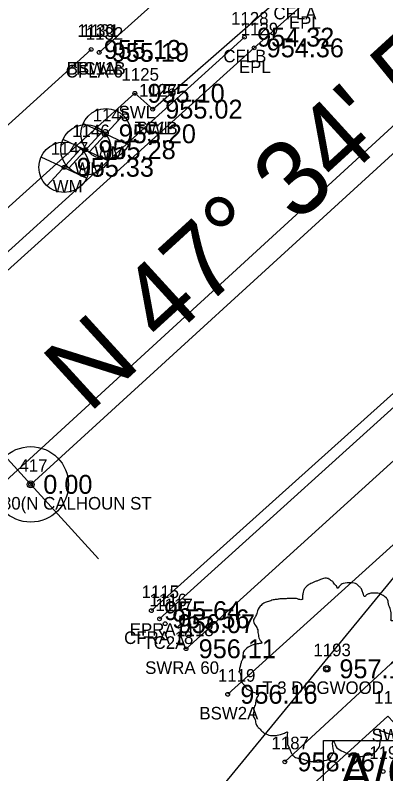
# Model space of a CAD drawing. Extents: x 1575382 to 1578175, y 1099175 to 1101955.
# Drawn here: x 1576354.3 to 1576383.7, y 1099534.1 to 1099594.4 of the extents above; entities that cross this region are included whole.
import ezdxf

# ---------------------------------------------------------------- set-up
doc = ezdxf.new("R2010")
doc.units = 0
for name, color, linetype in [('RD_EX_BldgApp', 7, 'Continuous'), ('RD_EX_BldgApp_txCode', 7, 'Continuous'), ('RD_EX_Conc', 7, 'Continuous'), ('RD_EX_Conc_txCode', 7, 'Continuous'), ('RD_EX_DR_Pipe', 7, 'Continuous'), ('RD_EX_Road', 7, 'Continuous'), ('RD_EX_Road_txCode', 7, 'Continuous'), ('RD_EX_TX_Conc_ELEV', 7, 'Continuous'), ('RD_EX_TX_Road_ELEV', 7, 'Continuous'), ('RD_EX_TX_UT_ELEV', 7, 'Continuous'), ('RD_EX_TX_VEG_ELEV', 7, 'Continuous'), ('RD_EX_UT', 7, 'Continuous'), ('RD_EX_UT_txCode', 7, 'Continuous'), ('RD_EX_VEG', 7, 'Continuous'), ('RD_EX_VEG_txCode', 7, 'Continuous'), ('RD_HC_Cl', 7, 'Continuous'), ('RD_HC_Data', 7, 'Continuous'), ('RD_HC_Data_Tic', 7, 'Continuous'), ('RD_HC_Survey_ELEV', 7, 'Continuous'), ('RD_HC_txCode', 7, 'Continuous'), ('RD_SMD_Locator', 7, 'Continuous')]:
    doc.layers.add(name, color=color, linetype=linetype)

msp = doc.modelspace()

# ---------------------------------------------------------------- linework, layer by layer
at = {"layer": 'RD_EX_BldgApp'}
msp.add_lwpolyline([(1576378.763, 1099531.771), (1576378.763, 1099536.771), (1576387.763, 1099536.771), (1576387.763, 1099531.771)], close=True, dxfattribs=at)
at = {"layer": 'RD_EX_Conc'}
for p, q in [((1576345.022, 1099567.755), (1576372.484, 1099592.673)), ((1576340.778, 1099574.008), (1576360.313, 1099591.697)), ((1576386.586, 1099545.179), (1576375.696, 1099535.084))]:
    msp.add_line(p, q, dxfattribs=at)
for points in [[(1576360.945, 1099591.467), (1576368.12, 1099597.926), (1576371.825, 1099601.361), (1576376.294, 1099605.493), (1576378.653, 1099607.482), (1576379.425, 1099608.864), (1576379.064, 1099610.368), (1576375.693, 1099614.257)], [(1576343.522, 1099569.964), (1576363.781, 1099588.213), (1576365.195, 1099586.953), (1576376.121, 1099596.515), (1576380.795, 1099600.714), (1576379.736, 1099601.846)], [(1576365.744, 1099546.452), (1576389.058, 1099567.543), (1576393.531, 1099571.514)], [(1576367.848, 1099544.074), (1576387.491, 1099561.904), (1576391.192, 1099565.202), (1576389.395, 1099567.132), (1576393.909, 1099571.093)], [(1576371.157, 1099540.455), (1576390.601, 1099558.016), (1576394.475, 1099561.498)], [(1576389.847, 1099541.582), (1576385.223, 1099537.281), (1576383.878, 1099538.711), (1576376.51, 1099532.017)]]:
    msp.add_lwpolyline(points, dxfattribs=at)
at = {"layer": 'RD_EX_DR_Pipe'}
msp.add_lwpolyline([(1576364.841, 1099525.95), (1576408.84, 1099579.579), (1576408.84, 1099579.579), (1576384.131, 1099602.876), (1576384.131, 1099602.876), (1576335.971, 1099659.822), (1576335.971, 1099659.822), (1576168.711, 1099756.104)], dxfattribs=at)
at = {"layer": 'RD_EX_Road'}
for points in [[(1576345.735, 1099566.974), (1576373.249, 1099591.824), (1576377.221, 1099595.34), (1576381.818, 1099599.483), (1576383.698, 1099601.102)], [(1576365.091, 1099547.103), (1576400.456, 1099578.873), (1576404.992, 1099582.283), (1576408.268, 1099583.268), (1576411.469, 1099582.29), (1576413.119, 1099580.849), (1576414.82, 1099582.112), (1576433.704, 1099559.004), (1576464.951, 1099521.111), (1576497.797, 1099481.911), (1576528.729, 1099444.459), (1576560.009, 1099406.61)]]:
    msp.add_lwpolyline(points, dxfattribs=at)
at = {"layer": 'RD_EX_UT'}
for p, q in [((1576173.795, 1099392.654), (1576417.784, 1099616.336)), ((1576360.14, 1099583.535), (1576362.807, 1099586.431)), ((1576359.658, 1099585.83), (1576363.289, 1099584.117)), ((1576358.539, 1099582.271), (1576361.207, 1099585.168)), ((1576358.058, 1099584.566), (1576361.689, 1099582.854)), ((1576356.806, 1099580.874), (1576359.474, 1099583.771)), ((1576356.325, 1099583.17), (1576359.956, 1099581.457))]:
    msp.add_line(p, q, dxfattribs=at)
for centre in [(1576361.492, 1099584.993), (1576359.891, 1099583.729), (1576358.158, 1099582.333)]:
    msp.add_circle(centre, 2, dxfattribs=at)
at = {"layer": 'RD_EX_VEG'}
for centre, radius in [((1576379.025, 1099542.481), 0.25), ((1576379.013, 1099542.462), 0.0001)]:
    msp.add_circle(centre, radius, dxfattribs=at)
for points in [[(1576379.157, 1099549.648), (1576378.857, 1099549.673), (1576378.533, 1099549.573), (1576378.283, 1099549.473), (1576378.058, 1099549.398), (1576377.833, 1099549.298), (1576377.533, 1099549.123), (1576377.308, 1099548.923), (1576377.183, 1099548.674), (1576377.133, 1099548.449), (1576377.083, 1099548.174), (1576377.083, 1099547.999), (1576376.958, 1099547.974), (1576376.808, 1099547.999), (1576376.558, 1099548.074), (1576376.308, 1099548.074), (1576376.059, 1099548.074), (1576375.709, 1099548.049), (1576375.359, 1099548.049), (1576375.084, 1099547.999), (1576374.759, 1099547.949), (1576374.384, 1099547.824), (1576374.034, 1099547.699), (1576373.735, 1099547.449), (1576373.485, 1099546.974), (1576373.36, 1099546.624), (1576373.21, 1099546.375), (1576373.36, 1099545.925), (1576373.535, 1099545.575), (1576373.56, 1099545.375), (1576373.635, 1099544.95), (1576373.735, 1099544.725), (1576373.86, 1099544.525), (1576373.785, 1099544.5), (1576373.41, 1099544.45), (1576373.11, 1099544.35), (1576372.685, 1099544.126), (1576372.46, 1099543.901), (1576372.36, 1099543.576), (1576372.335, 1099543.226), (1576372.235, 1099543.026), (1576372.16, 1099542.751), (1576372.135, 1099542.676), (1576372.085, 1099542.351), (1576372.185, 1099541.901), (1576372.21, 1099541.552), (1576372.335, 1099541.327), (1576372.485, 1099541.152), (1576372.66, 1099540.902), (1576373.06, 1099540.677), (1576373.385, 1099540.577), (1576373.585, 1099540.552), (1576373.41, 1099540.052), (1576373.36, 1099539.702), (1576373.235, 1099539.303), (1576373.235, 1099539.228), (1576373.185, 1099538.753), (1576373.335, 1099538.428), (1576373.41, 1099538.053), (1576373.585, 1099537.828), (1576373.86, 1099537.528), (1576374.184, 1099537.304), (1576374.684, 1099537.179), (1576375.084, 1099537.204), (1576375.659, 1099537.378), (1576375.909, 1099537.453), (1576375.884, 1099537.279), (1576375.909, 1099536.904), (1576375.909, 1099536.479), (1576376.059, 1099536.154), (1576376.159, 1099535.879), (1576376.308, 1099535.629), (1576376.633, 1099535.404), (1576377.033, 1099535.329), (1576377.458, 1099535.179), (1576377.908, 1099535.104), (1576378.408, 1099535.079), (1576379.007, 1099535.229), (1576379.282, 1099535.354), (1576379.382, 1099535.529), (1576379.582, 1099535.904), (1576379.532, 1099536.129), (1576379.557, 1099536.729), (1576379.657, 1099536.554), (1576379.832, 1099536.204), (1576380.332, 1099535.904), (1576380.732, 1099535.729), (1576381.206, 1099535.579), (1576381.506, 1099535.504), (1576381.981, 1099535.579), (1576382.356, 1099535.654), (1576382.731, 1099535.779), (1576383.031, 1099536.054), (1576383.205, 1099536.329), (1576383.255, 1099536.604), (1576383.33, 1099536.979), (1576383.38, 1099537.154)], [(1576383.38, 1099537.154), (1576383.305, 1099537.329), (1576383.255, 1099537.578), (1576383.33, 1099537.553), (1576383.505, 1099537.503), (1576383.78, 1099537.378), (1576384.005, 1099537.304), (1576384.33, 1099537.329), (1576384.605, 1099537.428), (1576385.055, 1099537.703), (1576385.33, 1099538.178), (1576385.604, 1099538.578), (1576385.679, 1099538.903), (1576385.629, 1099539.128), (1576385.604, 1099539.627), (1576385.404, 1099539.877), (1576385.354, 1099540.002), (1576385.255, 1099540.402), (1576385.33, 1099540.452), (1576385.604, 1099540.502), (1576385.979, 1099540.627), (1576386.254, 1099540.752), (1576386.479, 1099540.927), (1576386.554, 1099541.152), (1576386.529, 1099541.552), (1576386.579, 1099541.951), (1576386.504, 1099542.101), (1576386.404, 1099542.251), (1576386.329, 1099542.451), (1576386.179, 1099542.601), (1576386.079, 1099542.751), (1576385.979, 1099542.851), (1576385.854, 1099543.001), (1576385.679, 1099543.126), (1576385.529, 1099543.176), (1576385.479, 1099543.326), (1576385.629, 1099543.526), (1576385.679, 1099543.626), (1576385.704, 1099543.851), (1576385.929, 1099544.2), (1576385.979, 1099544.6), (1576385.929, 1099545.025), (1576385.879, 1099545.3), (1576385.729, 1099545.575), (1576385.529, 1099545.825), (1576385.404, 1099546), (1576385.23, 1099546.125), (1576384.905, 1099546.25), (1576384.655, 1099546.3), (1576384.305, 1099546.3), (1576384.105, 1099546.35), (1576384.13, 1099546.4), (1576384.13, 1099546.549), (1576384.13, 1099546.824), (1576384.055, 1099547.274), (1576383.905, 1099547.774), (1576383.905, 1099547.799), (1576383.805, 1099548.049), (1576383.58, 1099548.249), (1576383.405, 1099548.349), (1576383.205, 1099548.474), (1576382.956, 1099548.499), (1576382.656, 1099548.499), (1576382.381, 1099548.449), (1576382.181, 1099548.349), (1576382.006, 1099548.224), (1576381.931, 1099548.374), (1576381.831, 1099548.674), (1576381.781, 1099548.823), (1576381.631, 1099548.998), (1576381.406, 1099549.198), (1576380.956, 1099549.323), (1576380.332, 1099549.248), (1576380.032, 1099549.048), (1576379.882, 1099548.873), (1576379.832, 1099548.998), (1576379.632, 1099549.198), (1576379.532, 1099549.373), (1576379.357, 1099549.498), (1576379.207, 1099549.598), (1576379.107, 1099549.648)]]:
    msp.add_spline(points, degree=3, dxfattribs=at)
at = {"layer": 'RD_HC_Cl'}
msp.add_line((1576355.507, 1099557.135), (1576409.214, 1099606.208), dxfattribs=at)
at = {"layer": 'RD_HC_Data'}
for radius in [3, 0.282]:
    msp.add_circle((1576355.507, 1099557.135), radius, dxfattribs=at)
at = {"layer": 'RD_HC_Data_Tic'}
for q in [(1576350.111, 1099563.041), (1576360.904, 1099551.229)]:
    msp.add_line((1576355.507, 1099557.135), q, dxfattribs=at)
at = {"layer": 'RD_SMD_Locator'}
for centre in [(1576372.484, 1099592.673), (1576360.313, 1099591.697), (1576360.313, 1099591.697), (1576360.945, 1099591.467), (1576373.249, 1099591.824), (1576363.781, 1099588.213), (1576365.195, 1099586.953), (1576365.195, 1099586.953), (1576361.492, 1099584.993), (1576359.891, 1099583.729), (1576358.158, 1099582.333), (1576355.507, 1099557.135), (1576365.091, 1099547.103), (1576365.744, 1099546.452), (1576366.186, 1099546.067), (1576367.848, 1099544.074), (1576379.025, 1099542.481), (1576371.157, 1099540.455), (1576375.696, 1099535.084), (1576383.498, 1099534.323)]:
    msp.add_circle(centre, 0.15, dxfattribs=at)

# ---------------------------------------------------------------- texts
at = {"layer": 'RD_EX_BldgApp'}
msp.add_text('A/C', height=3, dxfattribs=at).set_placement((1576380.009, 1099532.775))
at = {"layer": 'RD_EX_BldgApp_txCode'}
msp.add_text('1190', height=1, dxfattribs=at).set_placement((1576382.395, 1099535.323))
at = {"layer": 'RD_EX_Conc_txCode'}
for s, p in [('CFLA', (1576374.789, 1099594.086)), ('1128', (1576371.421, 1099593.673)), ('1130', (1576359.211, 1099592.697)), ('1131', (1576359.534, 1099592.697)), ('1132', (1576359.882, 1099592.467)), ('CFLB', (1576370.807, 1099590.673)), ('CFLA 6', (1576358.291, 1099589.467)), ('BSW1B', (1576358.36, 1099589.697)), ('TC1A', (1576358.864, 1099589.697)), ('1125', (1576362.718, 1099589.213)), ('1126', (1576364.109, 1099587.953)), ('1127', (1576364.132, 1099587.953)), ('SWL', (1576362.489, 1099586.213)), ('TC1B', (1576363.762, 1099584.953)), ('SWL', (1576363.904, 1099584.953)), ('1116', (1576364.941, 1099547.452)), ('1117', (1576365.406, 1099547.067)), ('1118', (1576367.068, 1099545.074)), ('CFRA 18', (1576362.925, 1099544.452)), ('TC2A', (1576364.454, 1099544.067)), ('SWRA 60', (1576364.596, 1099542.074)), ('1119', (1576370.378, 1099541.455)), ('1186', (1576382.791, 1099539.711)), ('BSW2A', (1576368.905, 1099538.455)), ('SW2', (1576382.586, 1099536.711)), ('1187', (1576374.633, 1099536.084))]:
    msp.add_text(s, height=1, dxfattribs=at).set_placement(p)
at = {"layer": 'RD_EX_Road_txCode'}
for s, p in [('1129', (1576372.186, 1099592.824)), ('EPL', (1576376.017, 1099593.34)), ('EPL', (1576372.044, 1099589.824)), ('1115', (1576364.312, 1099548.103)), ('EPRA', (1576363.375, 1099545.103))]:
    msp.add_text(s, height=1, dxfattribs=at).set_placement(p)
at = {"layer": 'RD_EX_TX_Conc_ELEV'}
for s, p in [('954.32', (1576373.484, 1099591.923)), ('955.13', (1576361.313, 1099590.947)), ('955.13', (1576361.313, 1099590.947)), ('955.19', (1576361.945, 1099590.717)), ('955.10', (1576364.781, 1099587.463)), ('955.02', (1576366.195, 1099586.203)), ('955.02', (1576366.195, 1099586.203)), ('955.56', (1576366.744, 1099545.702)), ('956.07', (1576367.186, 1099545.317)), ('956.11', (1576368.848, 1099543.324)), ('956.16', (1576372.157, 1099539.705)), ('958.26', (1576376.696, 1099534.334))]:
    msp.add_text(s, height=1.5, dxfattribs=at).set_placement(p)
at = {"layer": 'RD_EX_TX_Road_ELEV'}
for s, p in [('954.36', (1576374.249, 1099591.074)), ('955.64', (1576366.091, 1099546.353))]:
    msp.add_text(s, height=1.5, dxfattribs=at).set_placement(p)
at = {"layer": 'RD_EX_TX_UT_ELEV'}
for s, p in [('955.20', (1576362.492, 1099584.243)), ('955.28', (1576360.891, 1099582.979)), ('955.33', (1576359.158, 1099581.583))]:
    msp.add_text(s, height=1.5, dxfattribs=at).set_placement(p)
at = {"layer": 'RD_EX_TX_VEG_ELEV'}
msp.add_text('957.19', height=1.5, dxfattribs=at).set_placement((1576380.025, 1099541.731))
at = {"layer": 'RD_EX_UT_txCode'}
for s, p in [('1145', (1576360.429, 1099585.993)), ('1146', (1576358.805, 1099584.729)), ('1147', (1576357.095, 1099583.333)), ('WM', (1576360.586, 1099582.993)), ('WM', (1576358.986, 1099581.729)), ('WM', (1576357.253, 1099580.333))]:
    msp.add_text(s, height=1, dxfattribs=at).set_placement(p)
at = {"layer": 'RD_EX_VEG_txCode'}
for s, p in [('1193', (1576377.962, 1099543.481)), ('T 3 DOGWOOD', (1576373.899, 1099540.481))]:
    msp.add_text(s, height=1, dxfattribs=at).set_placement(p)
at = {"layer": 'RD_HC_Data'}
msp.add_text('N 47%%d 34\' 54" E', height=6, rotation=42.41831, dxfattribs=at).set_placement((1576360.115, 1099562.699))
at = {"layer": 'RD_HC_Survey_ELEV'}
msp.add_text('0.00', height=1.5, dxfattribs=at).set_placement((1576356.507, 1099556.385))
at = {"layer": 'RD_HC_txCode'}
for s, p in [('417', (1576354.61, 1099558.135)), ('POT (10+00.00) S80(N CALHOUN ST', (1576342.334, 1099555.135))]:
    msp.add_text(s, height=1, dxfattribs=at).set_placement(p)

doc.saveas('drawing.dxf')
